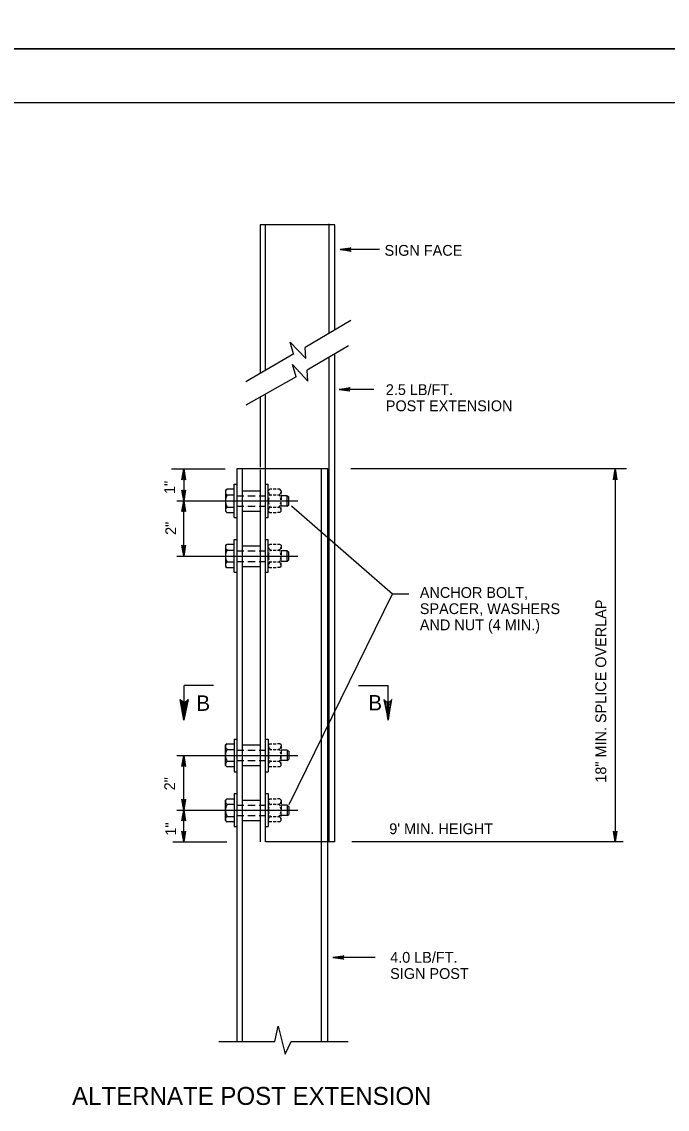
# Model space of a CAD drawing. Extents: x 644358 to 648627, y 294594 to 295782.
# Drawn here: x 644576.1 to 644755.6, y 294892.7 to 295195.1 of the extents above; entities that cross this region are included whole.
import ezdxf

# ---------------------------------------------------------------- set-up
doc = ezdxf.new("R2010")
doc.units = 0
for name, color, linetype in [('1', 7, 'Continuous'), ('2', 7, 'Continuous'), ('3', 7, 'Continuous'), ('4', 7, 'Continuous'), ('PLT-BNDY', 7, 'Continuous')]:
    doc.layers.add(name, color=color, linetype=linetype)

# ---------------------------------------------------------------- blocks, each defined once
blk = doc.blocks.new('RARROW')
at = {"layer": '3'}
blk.add_lwpolyline([(-2.2695, 0.285), (-2.184875, 0.12075), (0, 0), (-2.2695, 0.285), (-2.38575, 0.384625), (0, 0), (-2.183125, -0.108), (-2.262875, -0.2705), (0, 0), (-2.38575, -0.379125), (-2.262875, -0.2705)], dxfattribs=at)

msp = doc.modelspace()

# ---------------------------------------------------------------- linework, layer by layer
at = {"layer": '1'}
for p, q in [((644398.31, 295172.63), (645184.31, 295172.63)), ((644648.21, 295064.63), (644648.21, 295063.88)), ((644648.21, 295063.51), (644648.21, 295062.13)), ((644648.21, 295060.26), (644648.21, 295061.51)), ((644648.21, 295059.01), (644648.21, 295060.01)), ((644648.21, 295049.51), (644648.21, 295048.51)), ((644648.21, 295048.13), (644648.21, 295046.76)), ((644648.21, 295045.01), (644648.21, 295046.26)), ((644648.21, 295043.63), (644648.21, 295044.63)), ((644648.21, 294994.01), (644648.21, 294993.01)), ((644648.21, 294992.63), (644648.21, 294991.38)), ((644648.21, 294989.51), (644648.21, 294990.88)), ((644648.21, 294988.26), (644648.21, 294989.13)), ((644648.21, 294978.63), (644648.21, 294977.63)), ((644648.21, 294977.38), (644648.21, 294976.01)), ((644648.21, 294974.13), (644648.21, 294975.51)), ((644648.21, 294973.01), (644648.21, 294973.76))]:
    msp.add_line(p, q, dxfattribs=at)
for points in [[(644622.09, 295006.26), (644621.46, 295006.01), (644621.09, 295000.88), (644622.09, 295006.26), (644622.34, 295006.63), (644621.09, 295000.88), (644620.96, 295006.01), (644620.46, 295006.26), (644621.09, 295000.88), (644620.09, 295006.63), (644620.46, 295006.26)], [(644677.09, 295006.26), (644677.59, 295006.01), (644677.96, 295000.88), (644677.09, 295006.26), (644676.71, 295006.63), (644677.96, 295000.88), (644678.21, 295006.01), (644678.71, 295006.26), (644677.96, 295000.88), (644678.96, 295006.63), (644678.71, 295006.26)]]:
    msp.add_lwpolyline(points, dxfattribs=at)
for centre, radius, start, end in [((644645.47, 295064.34), 0.81, 184.8919, 254.2247), ((644647.69, 295061.85), 3.04, 146.6027, 154.678), ((644647.35, 295064.34), 0.81, 285.7753, 351.6558), ((644645.13, 295061.85), 3.04, 24.9174, 33.3973), ((644647.69, 295061.85), 3.04, 162.8799, 197.6126), ((644645.47, 295059.39), 0.81, 106.5107, 186.623), ((644647.69, 295061.85), 3.04, 205.6812, 213.3973), ((644647.35, 295059.39), 0.81, 358.7185, 73.4893), ((644645.13, 295061.85), 3.04, 326.6027, 334.9746), ((644645.13, 295061.85), 3.04, 6.0459, 16.9125), ((644645.13, 295061.85), 3.04, 344.0189, 354.4846), ((644645.47, 295049.01), 0.81, 184.8919, 254.2247), ((644647.69, 295046.52), 3.04, 146.6027, 154.678), ((644647.35, 295049.01), 0.81, 285.7753, 351.6558), ((644645.13, 295046.52), 3.04, 24.9174, 33.3973), ((644647.69, 295046.52), 3.04, 162.8799, 197.6126), ((644645.47, 295044.05), 0.81, 106.5107, 186.623), ((644647.69, 295046.52), 3.04, 205.6812, 213.3973), ((644647.35, 295044.05), 0.81, 358.7185, 73.4893), ((644645.13, 295046.52), 3.04, 326.6027, 334.9746), ((644645.13, 295046.52), 3.04, 6.0459, 16.9125), ((644645.13, 295046.52), 3.04, 344.0189, 354.4846), ((644645.47, 294993.59), 0.81, 173.377, 253.4893), ((644647.35, 294993.59), 0.81, 286.5107, 1.2815), ((644647.69, 294991.13), 3.04, 162.3874, 197.1201), ((644647.69, 294991.13), 3.04, 146.6027, 154.3188), ((644645.13, 294991.13), 3.04, 25.0254, 33.3973), ((644645.13, 294991.13), 3.04, 343.0875, 353.9541), ((644645.13, 294991.13), 3.04, 5.5154, 15.9811), ((644645.47, 294988.64), 0.81, 105.7753, 175.1081), ((644647.69, 294991.13), 3.04, 205.322, 213.3973), ((644647.35, 294988.64), 0.81, 8.3442, 74.2247), ((644645.13, 294991.13), 3.04, 326.6027, 335.0826), ((644645.47, 294978.26), 0.81, 173.377, 253.4893), ((644647.35, 294978.26), 0.81, 286.5107, 1.2815), ((644647.69, 294975.8), 3.04, 162.3874, 197.1201), ((644647.69, 294975.8), 3.04, 146.6027, 154.3188), ((644645.13, 294975.8), 3.04, 25.0254, 33.3973), ((644645.13, 294975.8), 3.04, 343.0875, 353.9541), ((644645.13, 294975.8), 3.04, 5.5154, 15.9811), ((644645.47, 294973.3), 0.81, 105.7753, 175.1081), ((644647.69, 294975.8), 3.04, 205.322, 213.3973), ((644647.35, 294973.3), 0.81, 8.3442, 74.2247), ((644645.13, 294975.8), 3.04, 326.6027, 335.0826)]:
    msp.add_arc(centre, radius, start, end, dxfattribs=at)
for centre, major_axis, start_param, end_param in [((644635.44, 295061.85), (0, -3.04), 4.129496, 5.295282), ((644633.44, 295064.34), (0, 0.81), 0.448108, 2.866262), ((644633.44, 295059.39), (0, -0.81), 3.429758, 5.835077), ((644635.44, 295046.52), (0, -3.04), 4.129496, 5.295282), ((644633.44, 295049.01), (0, 0.81), 0.448108, 2.866262), ((644633.44, 295044.05), (0, -0.81), 3.429758, 5.835077), ((644633.44, 294993.59), (0, 0.81), 0.448108, 2.853427), ((644635.44, 294991.13), (0, 3.04), 0.987904, 2.153689), ((644633.44, 294988.64), (0, -0.81), 3.416923, 5.835077), ((644633.44, 294978.26), (0, 0.81), 0.448108, 2.853427), ((644635.44, 294975.8), (0, 3.04), 0.987904, 2.153689), ((644633.44, 294973.3), (0, -0.81), 3.416923, 5.835077)]:
    msp.add_ellipse(centre, major_axis=major_axis, ratio=0.9, start_param=start_param, end_param=end_param, dxfattribs=at)
at = {"layer": '2'}
for p, q in [((644663.09, 295138.63), (644642.34, 295138.63)), ((644642.34, 295138.63), (644642.34, 295097.38)), ((644643.84, 295098.26), (644643.84, 295138.63)), ((644661.59, 295108.38), (644661.59, 295138.88)), ((644663.09, 295109.38), (644663.09, 295138.63)), ((644667.59, 295112.01), (644654.84, 295104.51)), ((644651.71, 295102.76), (644638.34, 295095.01)), ((644666.96, 295105.01), (644655.46, 295098.26)), ((644663.09, 294967.01), (644663.09, 295102.76)), ((644661.59, 294967.01), (644661.59, 295101.88)), ((644652.34, 295096.38), (644638.34, 295088.51)), ((644642.34, 295090.76), (644642.34, 295071.26)), ((644643.84, 294967.01), (644643.84, 295091.51)), ((644661.21, 295070.76), (644635.84, 295070.76)), ((644635.84, 295070.76), (644635.84, 294911.51)), ((644637.34, 295070.76), (644637.34, 294911.51)), ((644642.34, 295070.51), (644642.34, 294967.01)), ((644659.46, 294911.51), (644659.46, 295070.76)), ((644661.21, 294911.51), (644661.21, 295070.76)), ((644635.09, 295066.51), (644635.84, 295066.51)), ((644635.09, 295057.26), (644635.09, 295066.51)), ((644643.84, 295066.51), (644644.59, 295066.51)), ((644644.59, 295057.26), (644644.59, 295066.51)), ((644632.71, 295064.63), (644633.09, 295065.13)), ((644632.71, 295064.63), (644632.71, 295059.01)), ((644635.09, 295065.13), (644633.09, 295065.13)), ((644633.21, 295063.51), (644635.09, 295063.51)), ((644635.84, 295063.26), (644637.84, 295063.26)), ((644637.34, 295064.63), (644642.34, 295064.63)), ((644638.96, 295063.26), (644640.96, 295063.26)), ((644642.09, 295063.26), (644643.84, 295063.26)), ((644644.59, 295064.63), (644645.09, 295065.13)), ((644645.59, 295065.13), (644645.09, 295065.13)), ((644645.21, 295063.51), (644645.59, 295063.51)), ((644646.84, 295065.13), (644645.96, 295065.13)), ((644645.96, 295063.51), (644646.84, 295063.51)), ((644647.84, 295065.13), (644647.21, 295065.13)), ((644647.21, 295063.51), (644647.71, 295063.51)), ((644648.21, 295064.63), (644647.84, 295065.13)), ((644649.84, 295063.26), (644648.21, 295063.26)), ((644649.84, 295060.38), (644649.84, 295063.26)), ((644649.84, 295063.26), (644650.34, 295063.01)), ((644650.34, 295060.76), (644650.34, 295063.01)), ((644633.21, 295060.13), (644635.09, 295060.13)), ((644635.84, 295060.38), (644637.84, 295060.38)), ((644638.96, 295060.38), (644640.96, 295060.38)), ((644642.09, 295060.38), (644643.84, 295060.38)), ((644645.21, 295060.13), (644645.59, 295060.13)), ((644645.96, 295060.13), (644646.84, 295060.13)), ((644647.21, 295060.13), (644647.71, 295060.13)), ((644649.84, 295060.38), (644648.21, 295060.38)), ((644649.84, 295060.38), (644650.34, 295060.76)), ((644632.71, 295059.01), (644633.09, 295058.63)), ((644633.09, 295058.63), (644635.09, 295058.63)), ((644635.09, 295057.26), (644635.84, 295057.26)), ((644637.34, 295059.01), (644642.34, 295059.01)), ((644643.84, 295057.26), (644644.59, 295057.26)), ((644644.59, 295059.01), (644645.09, 295058.63)), ((644645.09, 295058.63), (644645.59, 295058.63)), ((644645.96, 295058.63), (644646.84, 295058.63)), ((644647.84, 295058.63), (644647.21, 295058.63)), ((644648.21, 295059.01), (644647.84, 295058.63)), ((644635.09, 295051.13), (644635.84, 295051.13)), ((644635.09, 295042.01), (644635.09, 295051.13)), ((644643.84, 295051.13), (644644.59, 295051.13)), ((644644.59, 295042.01), (644644.59, 295051.13)), ((644632.71, 295049.51), (644633.09, 295049.76)), ((644632.71, 295049.51), (644632.71, 295043.63)), ((644635.09, 295049.76), (644633.09, 295049.76)), ((644633.21, 295048.13), (644635.09, 295048.13)), ((644635.84, 295048.01), (644637.84, 295048.01)), ((644637.34, 295049.38), (644642.34, 295049.38)), ((644638.96, 295048.01), (644640.96, 295048.01)), ((644642.09, 295048.01), (644643.84, 295048.01)), ((644644.59, 295049.51), (644645.09, 295049.76)), ((644645.59, 295049.76), (644645.09, 295049.76)), ((644645.21, 295048.13), (644645.59, 295048.13)), ((644646.84, 295049.76), (644645.96, 295049.76)), ((644645.96, 295048.13), (644646.84, 295048.13)), ((644647.84, 295049.76), (644647.21, 295049.76)), ((644647.21, 295048.13), (644647.71, 295048.13)), ((644648.21, 295049.51), (644647.84, 295049.76)), ((644649.84, 295048.01), (644648.21, 295048.01)), ((644649.84, 295045.01), (644649.84, 295048.01)), ((644649.84, 295048.01), (644650.34, 295047.63)), ((644633.21, 295044.88), (644635.09, 295044.88)), ((644635.84, 295045.01), (644637.84, 295045.01)), ((644638.96, 295045.01), (644640.96, 295045.01)), ((644642.09, 295045.01), (644643.84, 295045.01)), ((644645.21, 295044.88), (644645.59, 295044.88)), ((644645.96, 295044.88), (644646.84, 295044.88)), ((644647.21, 295044.88), (644647.71, 295044.88)), ((644649.84, 295045.01), (644648.21, 295045.01)), ((644649.84, 295045.01), (644650.34, 295045.51)), ((644650.34, 295045.51), (644650.34, 295047.63)), ((644632.71, 295043.63), (644633.09, 295043.38)), ((644633.09, 295043.38), (644635.09, 295043.38)), ((644635.09, 295042.01), (644635.84, 295042.01)), ((644637.34, 295043.63), (644642.34, 295043.63)), ((644643.84, 295042.01), (644644.59, 295042.01)), ((644644.59, 295043.63), (644645.09, 295043.38)), ((644645.09, 295043.38), (644645.59, 295043.38)), ((644645.96, 295043.38), (644646.84, 295043.38)), ((644647.84, 295043.38), (644647.21, 295043.38)), ((644648.21, 295043.63), (644647.84, 295043.38)), ((644629.34, 295010.51), (644621.21, 295010.51)), ((644621.21, 295003.76), (644621.21, 295010.51)), ((644669.71, 295010.51), (644677.96, 295010.51)), ((644677.96, 295003.76), (644677.96, 295010.51)), ((644632.71, 294994.01), (644633.09, 294994.26)), ((644632.71, 294988.26), (644632.71, 294994.01)), ((644633.09, 294994.26), (644635.09, 294994.26)), ((644635.09, 294995.63), (644635.84, 294995.63)), ((644635.09, 294995.63), (644635.09, 294986.51)), ((644637.34, 294994.01), (644642.34, 294994.01)), ((644643.84, 294995.63), (644644.59, 294995.63)), ((644644.59, 294995.63), (644644.59, 294986.51)), ((644644.59, 294994.01), (644645.09, 294994.26)), ((644645.09, 294994.26), (644645.59, 294994.26)), ((644645.96, 294994.26), (644646.84, 294994.26)), ((644647.84, 294994.26), (644647.21, 294994.26)), ((644648.21, 294994.01), (644647.84, 294994.26)), ((644633.21, 294992.76), (644635.09, 294992.76)), ((644635.84, 294992.51), (644637.84, 294992.51)), ((644638.96, 294992.51), (644640.96, 294992.51)), ((644642.09, 294992.51), (644643.84, 294992.51)), ((644645.21, 294992.76), (644645.59, 294992.76)), ((644645.96, 294992.76), (644646.84, 294992.76)), ((644647.21, 294992.76), (644647.71, 294992.76)), ((644649.84, 294992.51), (644648.21, 294992.51)), ((644649.84, 294992.51), (644649.84, 294989.63)), ((644649.84, 294992.51), (644650.34, 294992.26)), ((644650.34, 294992.26), (644650.34, 294990.01)), ((644632.71, 294988.26), (644633.09, 294987.88)), ((644635.09, 294987.88), (644633.09, 294987.88)), ((644633.21, 294989.51), (644635.09, 294989.51)), ((644635.84, 294989.63), (644637.84, 294989.63)), ((644637.34, 294988.26), (644642.34, 294988.26)), ((644638.96, 294989.63), (644640.96, 294989.63)), ((644642.09, 294989.63), (644643.84, 294989.63)), ((644644.59, 294988.26), (644645.09, 294987.88)), ((644645.59, 294987.88), (644645.09, 294987.88)), ((644645.21, 294989.51), (644645.59, 294989.51)), ((644645.96, 294989.51), (644646.84, 294989.51)), ((644646.84, 294987.88), (644645.96, 294987.88)), ((644647.21, 294989.51), (644647.71, 294989.51)), ((644647.84, 294987.88), (644647.21, 294987.88)), ((644648.21, 294988.26), (644647.84, 294987.88)), ((644649.84, 294989.63), (644648.21, 294989.63)), ((644649.84, 294989.63), (644650.34, 294990.01)), ((644635.09, 294986.51), (644635.84, 294986.51)), ((644643.84, 294986.51), (644644.59, 294986.51)), ((644632.71, 294978.63), (644633.09, 294979.01)), ((644632.71, 294973.01), (644632.71, 294978.63)), ((644633.09, 294979.01), (644635.09, 294979.01)), ((644635.09, 294980.51), (644635.84, 294980.51)), ((644635.09, 294980.51), (644635.09, 294971.26)), ((644637.34, 294978.63), (644642.34, 294978.63)), ((644643.84, 294980.51), (644644.59, 294980.51)), ((644644.59, 294980.51), (644644.59, 294971.26)), ((644644.59, 294978.63), (644645.09, 294979.01)), ((644645.09, 294979.01), (644645.59, 294979.01)), ((644645.96, 294979.01), (644646.84, 294979.01)), ((644647.84, 294979.01), (644647.21, 294979.01)), ((644648.21, 294978.63), (644647.84, 294979.01)), ((644633.21, 294977.51), (644635.09, 294977.51)), ((644635.84, 294977.26), (644637.84, 294977.26)), ((644638.96, 294977.26), (644640.96, 294977.26)), ((644642.09, 294977.26), (644643.84, 294977.26)), ((644645.21, 294977.51), (644645.59, 294977.51)), ((644645.96, 294977.51), (644646.84, 294977.51)), ((644647.21, 294977.51), (644647.71, 294977.51)), ((644649.84, 294977.26), (644648.21, 294977.26)), ((644649.84, 294977.26), (644649.84, 294974.38)), ((644649.84, 294977.26), (644650.34, 294976.88)), ((644650.34, 294976.88), (644650.34, 294974.63)), ((644632.71, 294973.01), (644633.09, 294972.63)), ((644635.09, 294972.63), (644633.09, 294972.63)), ((644633.21, 294974.13), (644635.09, 294974.13)), ((644635.84, 294974.38), (644637.84, 294974.38)), ((644637.34, 294973.01), (644642.34, 294973.01)), ((644638.96, 294974.38), (644640.96, 294974.38)), ((644642.09, 294974.38), (644643.84, 294974.38)), ((644644.59, 294973.01), (644645.09, 294972.63)), ((644645.59, 294972.63), (644645.09, 294972.63)), ((644645.21, 294974.13), (644645.59, 294974.13)), ((644645.96, 294974.13), (644646.84, 294974.13)), ((644646.84, 294972.63), (644645.96, 294972.63)), ((644647.21, 294974.13), (644647.71, 294974.13)), ((644647.84, 294972.63), (644647.21, 294972.63)), ((644648.21, 294973.01), (644647.84, 294972.63)), ((644649.84, 294974.38), (644648.21, 294974.38)), ((644649.84, 294974.38), (644650.34, 294974.63)), ((644635.09, 294971.26), (644635.84, 294971.26)), ((644643.84, 294971.26), (644644.59, 294971.26)), ((644663.09, 294967.01), (644643.84, 294967.01)), ((644630.84, 294911.51), (644646.46, 294911.51)), ((644650.96, 294911.51), (644666.84, 294911.51))]:
    msp.add_line(p, q, dxfattribs=at)
for points in [[(644651.59, 295102.76), (644650.71, 295106.01), (644655.09, 295101.51), (644654.84, 295104.51)], [(644651.59, 295102.76), (644650.71, 295106.01), (644655.09, 295101.51), (644654.84, 295104.51)], [(644652.34, 295096.38), (644651.34, 295099.76), (644655.59, 295095.13), (644655.46, 295098.26)], [(644652.34, 295096.38), (644651.34, 295099.76), (644655.59, 295095.13), (644655.46, 295098.26)], [(644646.46, 294911.51), (644647.34, 294915.76), (644649.34, 294908.01), (644650.96, 294911.51)]]:
    msp.add_lwpolyline(points, dxfattribs=at)
at = {"layer": '4'}
for p, q in [((644675.54, 295131.76), (644664.59, 295131.76)), ((644674.01, 295092.88), (644664.34, 295092.88)), ((644617.71, 295070.76), (644632.59, 295070.76)), ((644621.09, 295070.76), (644621.09, 295061.88)), ((644744.21, 295070.76), (644667.59, 295070.76)), ((644741.09, 295070.76), (644741.09, 294967.01)), ((644619.21, 295061.88), (644652.84, 295061.88)), ((644621.09, 295046.51), (644621.09, 295061.88)), ((644651.09, 295060.51), (644679.21, 295036.01)), ((644619.21, 295046.51), (644652.84, 295046.51)), ((644650.46, 294977.38), (644679.21, 295036.01)), ((644679.21, 295036.01), (644683.75, 295036.01)), ((644619.21, 294991.01), (644652.84, 294991.01)), ((644621.09, 294975.88), (644621.09, 294991.01)), ((644619.21, 294975.88), (644652.84, 294975.88)), ((644621.09, 294967.01), (644621.09, 294975.88)), ((644618.09, 294967.01), (644633.09, 294967.01)), ((644743.34, 294967.01), (644667.84, 294967.01)), ((644674.39, 294934.88), (644662.59, 294934.88))]:
    msp.add_line(p, q, dxfattribs=at)
at = {"layer": 'PLT-BNDY'}
for points in [[(644358.31, 295781.63), (645199.31, 295781.63), (645199.31, 295187.63), (644358.31, 295187.63)], [(644358.31, 295187.63), (645199.31, 295187.63), (645199.31, 294593.63), (644358.31, 294593.63)]]:
    msp.add_lwpolyline(points, close=True, dxfattribs=at)

# ---------------------------------------------------------------- block references
at = {"layer": '2', "xscale": 1.2574347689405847, "yscale": 1.3092961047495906}
for p, rotation in [((644664.59, 295131.76), 180), ((644664.34, 295092.88), 180), ((644621.09, 295070.76), 89.99999999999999), ((644741.09, 295070.76), 89.99999999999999), ((644621.09, 295061.88), -90.00000000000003), ((644621.09, 295061.88), 89.99999999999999), ((644621.09, 295046.51), -90.00000000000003), ((644621.09, 294991.01), 89.99999999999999), ((644621.09, 294975.88), -90.00000000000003), ((644621.09, 294975.88), 89.99999999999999), ((644621.09, 294967.01), -90.00000000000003), ((644741.09, 294967.01), -90.00000000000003), ((644662.59, 294934.88), 180)]:
    msp.add_blockref('RARROW', p, dxfattribs=dict(at, rotation=rotation))

# ---------------------------------------------------------------- texts
at = {"layer": '2'}
msp.add_text('ALTERNATE POST EXTENSION', height=5, dxfattribs=at).set_placement((644590.06, 294893.87))
at = {"layer": '4'}
for s, height, p in [(' SIGN FACE', 3, (644675.84, 295130.04)), ('2.5 LB/FT.', 3, (644677.31, 295091.31)), ('POST EXTENSION', 3, (644677.31, 295086.81)), ('ANCHOR BOLT,', 3, (644686.77, 295034.88)), ('SPACER, WASHERS', 3, (644686.77, 295030.38)), ('AND NUT (4 MIN.)', 3, (644686.77, 295025.88)), ('B', 4.3, (644624.6, 295003.47)), ('B', 4.3, (644672.42, 295003.57)), ("9' MIN. HEIGHT", 3, (644678.26, 294969.18)), ('4.0 LB/FT.', 3, (644678.52, 294933.41)), ('SIGN POST ', 3, (644678.52, 294928.91))]:
    msp.add_text(s, height=height, dxfattribs=at).set_placement(p)
for s, p in [('1"', (644618.69, 295063.79)), ('2"', (644618.99, 295052.4)), ('18" MIN. SPLICE OVERLAP', (644738.6, 294983.5)), ('2"', (644618.69, 294981.37)), ('1"', (644618.99, 294968.78))]:
    msp.add_text(s, height=3, rotation=90, dxfattribs=at).set_placement(p)

doc.saveas('drawing.dxf')
